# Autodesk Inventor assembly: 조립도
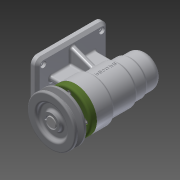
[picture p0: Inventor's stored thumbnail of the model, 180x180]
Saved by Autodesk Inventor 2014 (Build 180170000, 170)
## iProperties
Created: 2016-06
Part Number: 조립도
Document SubType Name: Assembly
Designer: 601-
Author: 601-
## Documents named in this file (12)
- C:\Users\601-\Desktop\460608V1018\조립도.iam
- C:\Users\601-\Desktop\460608V1018\V벨트풀리.ipt
- C:\Users\601-\Desktop\460608V1018\멈춤나사 M3x8.ipt
- C:\Users\601-\Desktop\460608V1018\베어링 6004.ipt
- C:\Users\601-\Desktop\460608V1018\베어링 51202.ipt
- C:\Users\601-\Desktop\460608V1018\본체.ipt
- C:\Users\601-\Desktop\460608V1018\볼트 M4 x 12.ipt
- C:\Users\601-\Desktop\460608V1018\어댑터슬리브.ipt
- C:\Users\601-\Desktop\460608V1018\오일 실.ipt
- C:\Users\601-\Desktop\460608V1018\축.ipt
- C:\Users\601-\Desktop\460608V1018\커버.ipt
- C:\Users\601-\Desktop\460608V1018\키 5 x 5 x 16.ipt
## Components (5 placed, 2 different names)
1. V벨트풀리:1 — Mate:2, Mate:15, Mate:16, Mate:21
2. ISO 4762 M4 x 12:1 — Insert:2
3. ISO 4762 M4 x 12:2
4. ISO 4762 M4 x 12:3
5. ISO 4762 M4 x 12:4
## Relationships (5: Mate 4, Insert 1)
- Mate:2: V벨트풀리:1
- Mate:15: V벨트풀리:1
- Mate:16: V벨트풀리:1
- Insert:2: ISO 4762 M4 x 12:1
- Mate:21: V벨트풀리:1
